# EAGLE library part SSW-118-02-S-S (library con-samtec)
THROUGH-HOLE .025" SQ POST SOCKET Source: Samtec SSW.pdf
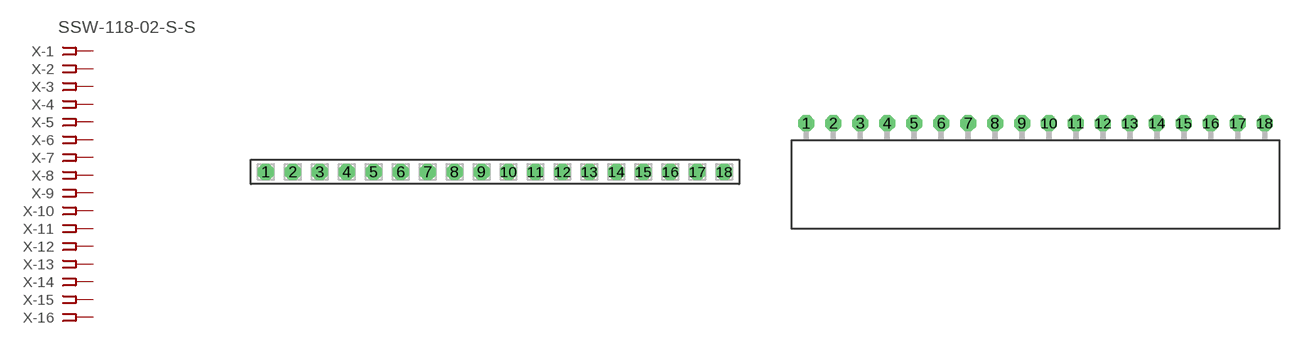
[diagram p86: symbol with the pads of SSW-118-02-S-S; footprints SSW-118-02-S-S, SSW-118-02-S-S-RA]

Designator prefix X; gates -1=FPINV -2=FPIN -3=FPIN -4=FPIN -5=FPIN -6=FPIN -7=FPIN -8=FPIN -9=FPIN -10=FPIN -11=FPIN -12=FPIN -13=FPIN -14=FPIN -15=FPIN -16=FPIN -17=FPIN -18=FPIN

## SSW-118-02-S-S (MPN: SSW-118-02-S-S; OC_FARNELL: unknown; OC_NEWARK: 11P9608)  [SSW-118-02-S-S]
1  -1:1  pas
2  -2:1  pas
3  -3:1  pas
4  -4:1  pas
5  -5:1  pas
6  -6:1  pas
7  -7:1  pas
8  -8:1  pas
9  -9:1  pas
10  -10:1  pas
11  -11:1  pas
12  -12:1  pas
13  -13:1  pas
14  -14:1  pas
15  -15:1  pas
16  -16:1  pas
17  -17:1  pas
18  -18:1  pas

## SSW-118-02-S-S-RA (MPN: SSW-118-02-S-S-RA; OC_FARNELL: unknown; OC_NEWARK: 11P9609)  [SSW-118-02-S-S-RA]
Pads as for SSW-118-02-S-S

## Footprint SSW-118-02-S-S (pad centres in mm)
THROUGH-HOLE .025" SQ POST SOCKET Source: Samtec SSW.pdf
drill 1 pad 1.5 octagon: 1 -21.59,0; 2 -19.05,0; 3 -16.51,0; 4 -13.97,0; 5 -11.43,0; 6 -8.89,0; 7 -6.35,0; 8 -3.81,0; 9 -1.27,0; 10 1.27,0; 11 3.81,0; 12 6.35,0; 13 8.89,0; 14 11.43,0; 15 13.97,0; 16 16.51,0; 17 19.05,0; 18 21.59,0

## Footprint SSW-118-02-S-S-RA (pad centres in mm)
THROUGH-HOLE .025" SQ POST SOCKET Source: Samtec SSW.pdf
drill 1 pad 1.5 octagon: 1 -21.59,1.524; 2 -19.05,1.524; 3 -16.51,1.524; 4 -13.97,1.524; 5 -11.43,1.524; 6 -8.89,1.524; 7 -6.35,1.524; 8 -3.81,1.524; 9 -1.27,1.524; 10 1.27,1.524; 11 3.81,1.524; 12 6.35,1.524; 13 8.89,1.524; 14 11.43,1.524; 15 13.97,1.524; 16 16.51,1.524; 17 19.05,1.524; 18 21.59,1.524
